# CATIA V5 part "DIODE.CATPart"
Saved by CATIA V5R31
Part number: DIODE
Source: Unknown
Bounding box of the stored display mesh (mm): x -1.75 to 1.75, y -0.8 to 0.8, z 0 to 0.8
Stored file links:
  \\solize.local\damia\dept\DDE_Design\10_order\2305701_JAMA_変換検証STEP3_お手本モデル作成\work\03_東洋電装_スイッチ\10_CATIA_V5\DIODE.CATPart
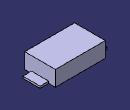
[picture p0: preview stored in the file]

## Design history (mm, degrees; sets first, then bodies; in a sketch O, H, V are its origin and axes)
WSupportSet1: ActiveGrid {3dwsupport RefPoint {point stored without definition}, 3DWOS ({wsupport Support xy-plane, RefPoint {3dwsupport}, GridIn {cartgrid Value 100, Stepbid1 0, Value 100, Stepbid2 0, Direction (1, 0, 0)}, GeometricData ({line type PtDir, Direction (1, 0, 0), Support xy-plane}; {line type PtDir, Direction (0, 1, 0), Support xy-plane})}; {wsupport Support yz-plane, RefPoint {3dwsupport}, GridIn {cartgrid Value 100, Stepbid1 0, Value 100, Stepbid2 0, Direction (0, 1, 0)}, GeometricData ({line type PtDir, Direction (0, 1, 0), Support yz-plane}; {line type PtDir, Direction (0, 0, 1), Support yz-plane})}; {wsupport Support zx-plane, RefPoint {3dwsupport}, GridIn {cartgrid Value 100, Stepbid1 0, Value 100, Stepbid2 0, Direction (0, 0, 1)}, GeometricData ({line type PtDir, Direction (0, 0, 1), Support zx-plane}; {line type PtDir, Direction (1, 0, 0), Support zx-plane})}), GeometricData ({line type PtDir, RefPoint {point stored without definition}, Direction (1, 0, 0), Support xy-plane}; {line type PtDir, RefPoint {point stored without definition}, Direction (0, 1, 0), Support xy-plane}; {line type PtDir, RefPoint {point stored without definition}, Direction (0, 1, 0), Support yz-plane}; {line type PtDir, RefPoint {point stored without definition}, Direction (0, 0, 1), Support yz-plane}; {line type PtDir, RefPoint {point stored without definition}, Direction (0, 0, 1), Support zx-plane}; {line type PtDir, RefPoint {point stored without definition}, Direction (1, 0, 0), Support zx-plane})}
Body1 (main body)
  Solid1 "PartBody": solid without history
